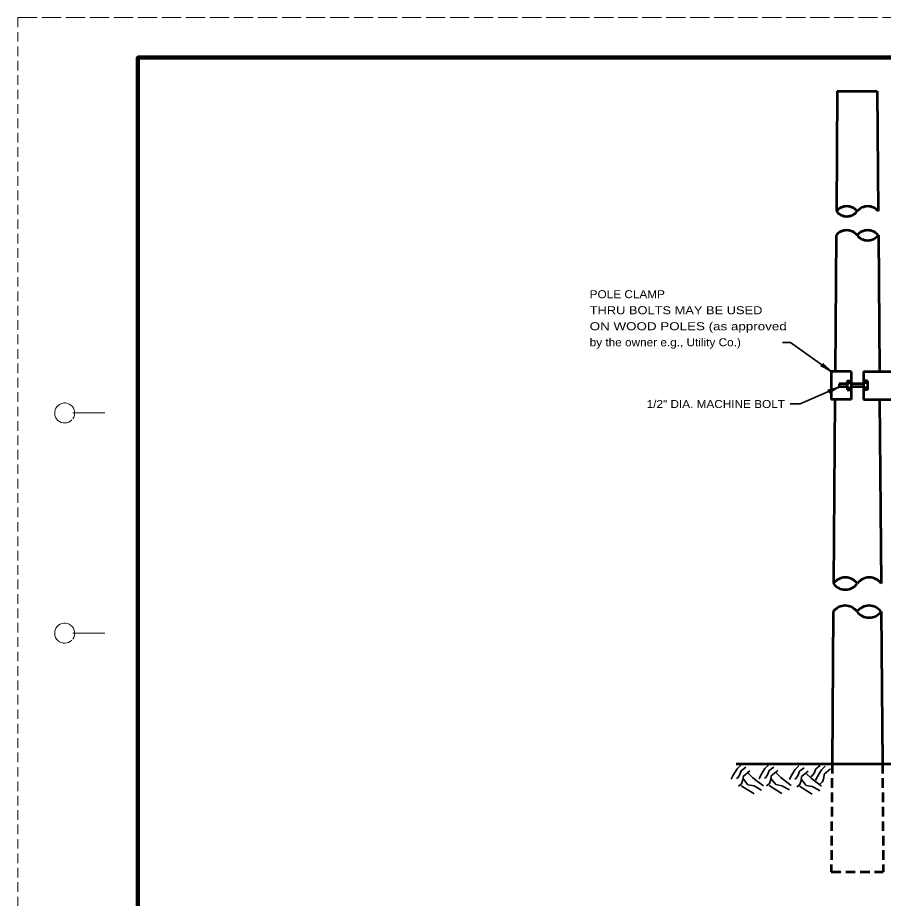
# Model space of a CAD drawing. Extents: x -368 to 312, y -34 to 406.
# Drawn here: x -368 to -151.6, y 186 to 406 of the extents above; entities that cross this region are included whole.
import ezdxf
from ezdxf.enums import TextEntityAlignment as Align

# ---------------------------------------------------------------- set-up
doc = ezdxf.new("R2010")
doc.units = 0
doc.header["$LTSCALE"] = 0.8
doc.linetypes.add('LONG_DASHED', pattern=[7.5, 6, -1.5])
doc.linetypes.add('MEDIUM_DASHED', pattern=[4.5, 3, -1.5])
doc.layers.add('1', color=7, linetype='Continuous', lineweight=53)
doc.layers.add('61', color=7, linetype='Continuous', lineweight=35)

msp = doc.modelspace()

# ---------------------------------------------------------------- linework, layer by layer
at = {"layer": '1', "linetype": 'MEDIUM_DASHED', "lineweight": 13}
msp.add_line((-367.9015, 406.0392), (-367.9615, -34.0007), dxfattribs=at)
at = {"layer": '1'}
for p, q in [((-163.1663, 387.6552), (-163.3971, 357.6552)), ((-163.1663, 387.6552), (-153.1663, 387.6552)), ((-153.1663, 387.6552), (-152.9355, 357.6552)), ((-163.4433, 351.6552), (-163.7047, 317.6552)), ((-152.8894, 351.6552), (-152.6278, 317.6552)), ((-159.7048, 317.6552), (-164.7048, 317.6552)), ((-164.7048, 317.6552), (-164.7048, 310.6552)), ((-159.7048, 317.6552), (-159.7048, 310.6552)), ((-156.622, 317.6552), (-156.622, 310.6552)), ((-156.622, 317.6552), (-148.622, 317.6552)), ((-160.7048, 315.2802), (-159.7048, 315.2802)), ((-160.7048, 315.2802), (-160.7048, 313.0302)), ((-160.7048, 314.7802), (-159.7048, 314.7802)), ((-155.622, 315.2802), (-156.622, 315.2802)), ((-155.622, 314.7802), (-156.622, 314.7802)), ((-155.622, 315.2802), (-155.622, 313.0302)), ((-160.7048, 314.5302), (-162.7048, 314.5302)), ((-162.7048, 314.5302), (-162.7048, 313.7802)), ((-160.7048, 313.7802), (-162.7048, 313.7802)), ((-160.7048, 313.5302), (-159.7048, 313.5302)), ((-160.7048, 313.0302), (-159.7048, 313.0302)), ((-156.622, 314.5302), (-159.7048, 314.5302)), ((-156.622, 313.7802), (-159.7048, 313.7802)), ((-155.622, 313.5302), (-156.622, 313.5302)), ((-155.622, 313.0302), (-156.622, 313.0302)), ((-159.7048, 310.6552), (-164.7048, 310.6552)), ((-163.7587, 310.6552), (-164.1125, 264.6552)), ((-156.622, 310.6552), (-148.622, 310.6552)), ((-152.574, 310.6552), (-152.2202, 264.6552)), ((-164.1663, 257.6552), (-164.4587, 219.6552)), ((-152.1663, 257.6552), (-151.874, 219.6552)), ((-188.4587, 219.6552), (-124.874, 219.6552))]:
    msp.add_line(p, q, dxfattribs=at)
at = {"layer": '1', "linetype": 'MEDIUM_DASHED'}
for p, q in [((-164.4587, 219.6552), (-164.6663, 192.6552)), ((-151.874, 219.6552), (-151.6663, 192.6552)), ((-164.6663, 192.6552), (-151.6663, 192.6552))]:
    msp.add_line(p, q, dxfattribs=at)
at = {"layer": '1', "lineweight": 35}
for points in [[(-164.7048, 317.6552), (-174.8232, 324.8839), (-176.8814, 324.8839)], [(-162.7048, 313.7802), (-172.4709, 309.5892), (-174.9702, 309.5892)], [(-187.2875, 219.2902), (-188.2182, 218.3593), (-189.2153, 216.7632), (-189.6807, 215.8323)], [(-186.0244, 218.7583), (-187.1546, 217.8937), (-187.4869, 216.9627), (-188.0187, 216.1648), (-188.3511, 215.9653)], [(-185.0273, 217.8937), (-186.6227, 216.5637), (-186.7557, 215.6328), (-187.0881, 214.6353), (-187.8193, 214.0368)], [(-180.3076, 219.3567), (-181.2382, 218.4257), (-182.2354, 216.8297), (-182.7007, 215.8988)], [(-179.0445, 218.8247), (-180.1747, 217.9603), (-180.507, 217.0292), (-181.0388, 216.2313), (-181.3712, 216.0318)], [(-178.0474, 217.9603), (-179.6428, 216.6302), (-179.7757, 215.6993), (-180.1082, 214.7018), (-180.8394, 214.1033)], [(-172.7292, 219.1572), (-173.6598, 218.2262), (-174.657, 216.6302), (-175.1223, 215.6993)], [(-171.4661, 218.6252), (-172.5962, 217.7608), (-172.9286, 216.8297), (-173.4604, 216.0318), (-173.7927, 215.8323)], [(-167.4109, 219.2237), (-168.5411, 218.3593), (-168.8734, 217.4282), (-169.4052, 216.6303), (-169.7376, 216.4308)], [(-166.2144, 219.0242), (-167.1451, 218.0932), (-168.1422, 216.4972), (-168.6076, 215.5663)], [(-164.8184, 218.3593), (-166.4138, 217.0292), (-166.5468, 216.0983), (-166.8792, 215.1008), (-167.6104, 214.5023)], [(-186.6227, 215.8323), (-185.4927, 214.3693), (-183.9637, 214.1033), (-182.2353, 213.1724), (-182.1688, 212.9729)], [(-185.4262, 217.2952), (-184.2296, 216.1648), (-183.0995, 215.2338), (-181.637, 214.1698)], [(-179.6428, 215.8988), (-178.5127, 214.4358), (-176.9837, 214.1698), (-175.2553, 213.2389), (-175.1889, 213.0394)], [(-178.4462, 217.3618), (-177.2497, 216.2313), (-176.1196, 215.3003), (-174.6571, 214.2363)], [(-170.469, 217.7608), (-172.0644, 216.4307), (-172.1973, 215.4998), (-172.5298, 214.5023), (-173.261, 213.9038)], [(-172.0644, 215.6993), (-170.9343, 214.2363), (-169.4053, 213.9703), (-167.6769, 213.0394), (-167.6105, 212.8399)], [(-170.8678, 217.1623), (-169.6712, 216.0318), (-168.5412, 215.1008), (-167.0787, 214.0368)], [(-187.1546, 214.1698), (-184.429, 212.4409), (-183.9637, 212.1749)], [(-180.1747, 214.2363), (-177.4491, 212.5074), (-176.9837, 212.2414)], [(-172.5962, 214.0368), (-169.8707, 212.3079), (-169.4053, 212.0419)]]:
    msp.add_lwpolyline(points, dxfattribs=at)
at = {"layer": '1'}
for centre, radius, start, end in [((-160.7817, 355.5698), 3.3465, 38.6004, 141.3996), ((-155.5415, 355.5698), 3.3465, 38.6004, 141.3996), ((-160.7817, 359.743), 3.3465, 218.6004, 321.3996), ((-160.8279, 349.5673), 3.3465, 38.6004, 141.3996), ((-155.5876, 349.5673), 3.3465, 38.6004, 141.3996), ((-155.5876, 353.7405), 3.3465, 218.6004, 321.3996), ((-161.1394, 262.4582), 3.7066, 36.66818, 143.33182), ((-161.1394, 266.8687), 3.7066, 216.66818, 323.33182), ((-155.1734, 262.4582), 3.7066, 36.66818, 143.33182), ((-161.1933, 255.4417), 3.7066, 36.66818, 143.33182), ((-155.2272, 255.4417), 3.7066, 36.66818, 143.33182), ((-155.2272, 259.8522), 3.7066, 216.66818, 323.33182)]:
    msp.add_arc(centre, radius, start, end, dxfattribs=at)
at = {"layer": '1', "lineweight": 40}
for centre, major_axis, ratio, start_param, end_param in [((-165.7533, 318.0647), (1.5438, -0.911), 0.122415, 0.89635335, 3.14159265), ((-165.7533, 318.0647), (1.5438, -0.911), 0.122415, 0.89635335, 3.14159265), ((-165.4936, 318.4787), (1.3271, -1.164), 0.07063, 3.14071475, 5.41810995), ((-165.4936, 318.4787), (1.3271, -1.164), 0.07063, 3.14071475, 5.41810995), ((-163.818, 313.5327), (-1.6834, -0.5313), 0.07063, 6.28230741, 8.55970261), ((-163.818, 313.5327), (-1.6834, -0.5313), 0.07063, 6.28230741, 8.55970261), ((-163.5986, 313.0959), (1.5794, 0.8477), 0.122415, 0.89635335, 3.14159265), ((-163.5986, 313.0959), (1.5794, 0.8477), 0.122415, 0.89635335, 3.14159265)]:
    msp.add_ellipse(centre, major_axis=major_axis, ratio=ratio, start_param=start_param, end_param=end_param, dxfattribs=at)
at = {"layer": '61', "linetype": 'LONG_DASHED', "lineweight": 13}
msp.add_line((-367.9015, 406.0392), (312.1185, 406.0392), dxfattribs=at)
at = {"layer": '61', "lineweight": 13}
for p, q in [((-354.1815, 307.2792), (-346.2015, 307.2992)), ((-354.2015, 252.2792), (-346.2015, 252.2792))]:
    msp.add_line(p, q, dxfattribs=at)
at = {"layer": '61', "lineweight": 158}
msp.add_lwpolyline([(301.1385, 396.0392), (-337.9015, 396.0392), (-337.9015, -23.9808)], dxfattribs=at)
at = {"layer": '61', "lineweight": 13}
for centre, end in [((-356.2037, 307.2805), 316.23216), ((-356.2037, 252.2805), 315.37577)]:
    msp.add_arc(centre, 2.5, 323.13009, end, dxfattribs=at)

# ---------------------------------------------------------------- texts
at = {"layer": '1'}
for s, width, p in [('POLE CLAMP', 1.1, (-225.0271, 335.9402)), ('THRU BOLTS MAY BE USED', 1.2, (-225.0271, 331.9402)), ('ON WOOD POLES (as approved', 1.25, (-225.0271, 327.9402)), ('by the owner e.g., Utility Co.)', 1.1, (-225.0271, 323.9402))]:
    msp.add_text(s, height=2, dxfattribs=dict(at, width=width)).set_placement(p)
at = {"layer": '1', "width": 1.1}
msp.add_text('1/2" DIA. MACHINE BOLT', height=2, dxfattribs=at).set_placement((-193.5144, 308.5132), align=Align.CENTER)

doc.saveas('drawing.dxf')
